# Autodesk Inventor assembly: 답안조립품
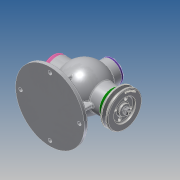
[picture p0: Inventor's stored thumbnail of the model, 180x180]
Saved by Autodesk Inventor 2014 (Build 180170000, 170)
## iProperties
Created: 2020-08
Part Number: 답안조립품
Document SubType Name: Assembly
Designer: kb542-17
Author: kb542-17
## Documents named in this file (18)
- C:\Users\kb542-17\Desktop\700806V1035\답안조립품.iam
- C:\Users\kb542-17\Desktop\700806V1035\본체.ipt
- C:\Users\kb542-17\Desktop\700806V1035\볼트 M4.ipt
- C:\Users\kb542-17\Desktop\700806V1035\상부커버.ipt
- C:\Users\kb542-17\Desktop\700806V1035\슬라이드.ipt
- C:\Users\kb542-17\Desktop\700806V1035\앞커버.ipt
- C:\Users\kb542-17\Desktop\700806V1035\오일 실 15 30 7.ipt
- C:\Users\kb542-17\Desktop\700806V1035\칼라.ipt
- C:\Users\kb542-17\Desktop\700806V1035\키 3x3x12.ipt
- C:\Users\kb542-17\Desktop\700806V1035\편심축.ipt
- C:\Users\kb542-17\Desktop\700806V1035\V-벨트풀리.ipt
- C:\Users\kb542-17\Desktop\700806V1035\너트 M8.ipt
- C:\Users\kb542-17\Desktop\700806V1035\뒤커버.ipt
- C:\Users\kb542-17\Desktop\700806V1035\멈춤링 15x1.ipt
- C:\Users\kb542-17\Desktop\700806V1035\멈춤링 35x1.6.ipt
- 멈춤링 35x1.6.ipt
- C:\Users\kb542-17\Desktop\700806V1035\베어링 6202.ipt
- 베어링 6202.ipt
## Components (1 placed, 1 different names)
1. V-벨트풀리:1
